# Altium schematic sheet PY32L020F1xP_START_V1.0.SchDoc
size A4
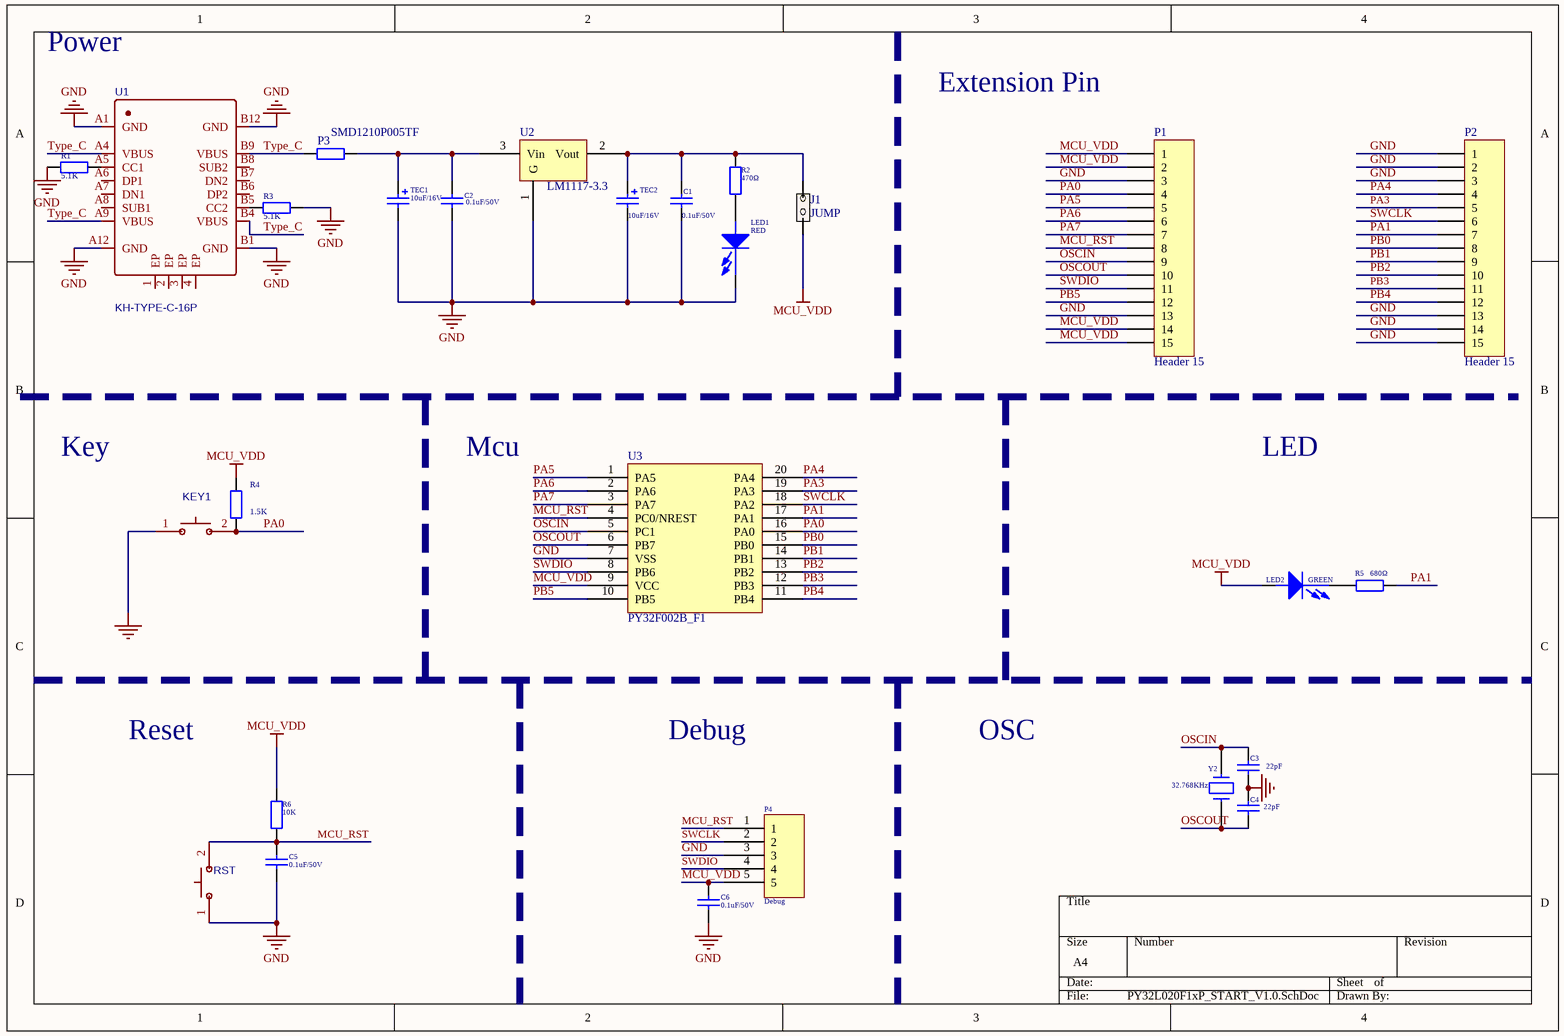
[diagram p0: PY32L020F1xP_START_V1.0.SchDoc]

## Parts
C1  0.1uF/50V  [0603C]
C2  0.1uF/50V  [0603C]
C3  22pF  [0603C]
C4  22pF  [0603C]
C5  0.1uF/50V  [0603C]
C6  0.1uF/50V  [0603C]
J1  JUMP  [HDR1X2]
KEY1  1TS002B-2600-5001  [SW]  (value not drawn)
LED1  RED  [0603_LED]
LED2  GREEN  [0603_LED]
P1  Header 15  [HDR1X15]
P2  Header 15  [HDR1X15]
P3  SMD1210P005TF  [SDM1210P005TF]
P4  Debug  [HDR1X5]
R1  5.1K  [0603R]
R2  470Ω  [0603R]
R3  5.1K  [0603R]
R4  1.5K  [0603R]
R5  680Ω  [0603R]
R6  10K  [0603R]
RST  1TS002B-2600-5001  [SW]  (value not drawn)
TEC1  value 10uF/16V  [0603]  (hidden comment: 10uF)
TEC2  value 10uF/16V  [0603]  (hidden comment: 10uF)
U1  KH-TYPE-C-16P  [USB-C-SMD_KH-TYPE-C-16P]
U2  LM1117-3.3  [LM1117-3.3]
U3  PY32F002B_F1  [TSSOP20]
Y2  32.768KHz  [32768KHZ_2]

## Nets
GND: C1.1 C2.1 C3.1 C4.2 C5.1 C6.1 KEY1.1(A) LED1.2(CATHODE) P1.3 P1.13 P2.1 P2.2 P2.3 P2.13 P2.14 P2.15 P4.3 R1.1 R3.2 RST.1(A) TEC1.2 TEC2.2 U1.A1(GND) U1.A12(GND) U1.B1(GND) U1.B12(GND) U2.1(G) U3.7(VSS)
MCU_VDD: C6.2 J1.1 LED2.1(ANODE) P1.1 P1.2 P1.14 P1.15 P4.5 R4.1 R6.2 U3.9(VCC)
MCU_RST: C5.2 P1.8 P4.1 R6.1 RST.2(B) U3.4(PC0/NREST)
OSCIN: C3.2 P1.9 U3.5(PC1) Y2.1
OSCOUT: C4.1 P1.10 U3.6(PB7) Y2.2
PA0: KEY1.2(B) P1.4 R4.2 U3.16(PA0)
PA1: P2.7 R5.2 U3.17(PA1)
PA3: P2.5 U3.19(PA3)
PA4: P2.4 U3.20(PA4)
PA5: P1.5 U3.1(PA5)
PA6: P1.6 U3.2(PA6)
PA7: P1.7 U3.3(PA7)
PB0: P2.8 U3.15(PB0)
PB1: P2.9 U3.14(PB1)
PB2: P2.10 U3.13(PB2)
PB3: P2.11 U3.12(PB3)
PB4: P2.12 U3.11(PB4)
PB5: P1.12 U3.10(PB5)
SWCLK: P2.6 P4.2 U3.18(PA2)
SWDIO: P1.11 P4.4 U3.8(PB6)
Type_C: P3.1 U1.A4(VBUS) U1.A9(VBUS) U1.B4(VBUS) U1.B9(VBUS)
NetC1_2: C1.2 J1.2 R2.1 TEC2.1 U2.2(Vout)
NetC2_2: C2.2 P3.2 TEC1.1 U2.3(Vin)
NetLED1_1: LED1.1(ANODE) R2.2
NetLED2_2: LED2.2(CATHODE) R5.1
NetR1_2: R1.2 U1.A5(CC1)
NetR3_1: R3.1 U1.B5(CC2)

Not connected (* = marked no-connect by the designer): U1 1(EP) 2(EP) 3(EP) 4(EP) A6(DP1) A7(DN1) A8(SUB1) B6(DP2) B7(DN2) B8(SUB2)

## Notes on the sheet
- Power
- Extension Pin
- Key
- Mcu
- LED
- Reset
- Debug
- OSC

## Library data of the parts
C1 C3 C4 = Cap: Capacitor
C2 C5 C6 = CAP: Capacitor; Value: 2.2uF
KEY1 RST = 1TS002B-2600-5001: BOM_Manufacturer: HYP; Contributor: LCSC
LED1 LED2 = PDI-E803_Dup1
P1 P2 = Header 15: Header, 15-Pin
P4 = CON5
R1 R3 = Res_1: Resistor; 器件封装(外观): 0603; Value: 10K
R2 R4 R5 = Res: Resistor; 器件封装(外观): 0603; Value: 10K
R6 = Res: Resistor; 器件封装(外观): 0603
TEC1 TEC2 = 贴片钽电容: 器件封装(外观): 3528
U1 = KH-TYPE-C-16P: BOM_Manufacturer: Shenzhen Kinghelm Elec; Contributor: LCSC
Y2 = CRYSTAL_1: Crystal; Value: X503225MSB2GI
